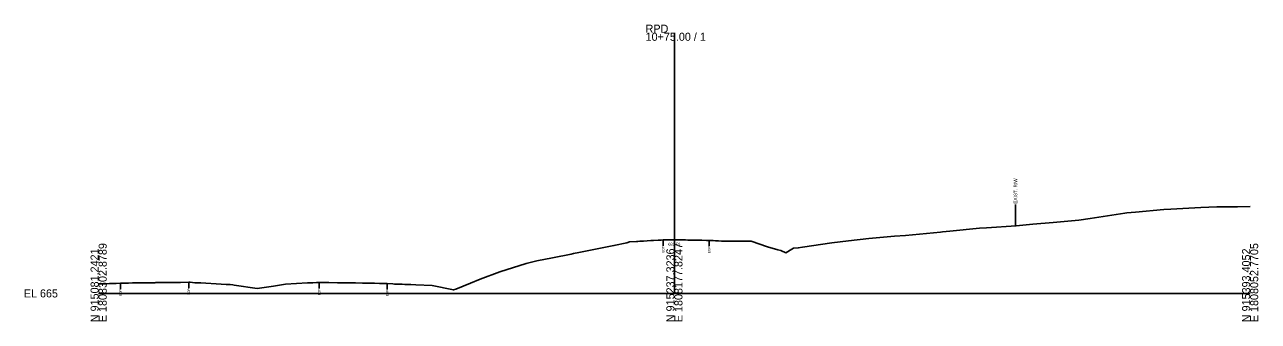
# Model space of a CAD drawing. Extents: x -26 to 403, y -10 to 8517.
# Drawn here: x -25.7 to 402.8, y 1490.3 to 1593.3 of the extents above; entities that cross this region are included whole.
import ezdxf

# ---------------------------------------------------------------- set-up
doc = ezdxf.new("R2010")
doc.units = 0
for name, color, linetype in [('Exist Cross Section Cell', 7, 'Continuous'), ('Exist XS Center Line Elevation Label', 7, 'Continuous'), ('Exist XS Ground Line', 7, 'Continuous'), ('Old_Level_10', 7, 'Continuous')]:
    doc.layers.add(name, color=color, linetype=linetype)

msp = doc.modelspace()

# ---------------------------------------------------------------- linework, layer by layer
at = {"layer": 'Exist Cross Section Cell'}
for p, q in [((200, 1500), (200, 1590.53)), ((0, 1500), (200, 1500)), ((200, 1500), (400, 1500))]:
    msp.add_line(p, q, dxfattribs=at)
at = {"layer": 'Exist XS Ground Line'}
msp.add_lwpolyline([(0, 1503.29), (0.81, 1503.31), (2.82, 1503.38), (3.79, 1503.4), (5.02, 1503.41), (6.09, 1503.46), (7.6, 1503.56), (9.3, 1503.58), (10.4, 1503.6), (11.79, 1503.62), (12.49, 1503.63), (15.66, 1503.67), (17.46, 1503.7), (18.88, 1503.73), (19.48, 1503.73), (19.82, 1503.74), (20.9, 1503.75), (22.07, 1503.77), (22.82, 1503.78), (23.76, 1503.79), (24.61, 1503.8), (25.3, 1503.81), (27.76, 1503.82), (28.47, 1503.83), (31.32, 1503.86), (31.74, 1503.85), (33.46, 1503.71), (35.11, 1503.73), (35.49, 1503.72), (42.58, 1503.25), (44.29, 1503.14), (44.97, 1503.1), (45.73, 1503.05), (46.56, 1502.99), (47.05, 1502.9), (55.02, 1501.67), (60.72, 1502.5), (64.91, 1503.2), (72.56, 1503.66), (73.06, 1503.66), (74.4, 1503.68), (75.71, 1503.74), (76.62, 1503.8), (79.99, 1503.75), (82.96, 1503.73), (83.3, 1503.73), (83.72, 1503.72), (85.06, 1503.7), (86.13, 1503.69), (86.85, 1503.68), (88, 1503.66), (88.66, 1503.65), (89.17, 1503.64), (91.69, 1503.6), (92.19, 1503.59), (92.57, 1503.58), (93.95, 1503.56), (95.82, 1503.53), (97.51, 1503.49), (98.99, 1503.46), (99.48, 1503.46), (100.27, 1503.44), (102.15, 1503.3), (102.83, 1503.25), (103.68, 1503.22), (104.64, 1503.19), (105.4, 1503.16), (106.42, 1503.12), (107.69, 1503.08), (108.44, 1503.06), (110.23, 1503), (115.82, 1502.76), (123.25, 1501.2), (124.06, 1501.51), (129.22, 1503.6), (132.55, 1504.96), (139.36, 1507.49), (148.54, 1510.35), (152.17, 1511.28), (157.67, 1512.41), (164.13, 1513.67), (164.99, 1513.81), (166.81, 1514.18), (177.8, 1516.36), (179.01, 1516.62), (183.44, 1517.62), (184.42, 1517.86), (186.82, 1518.02), (187.31, 1518.06), (188.04, 1518.1), (189.29, 1518.19), (191.84, 1518.34), (192.75, 1518.4), (194.39, 1518.46), (195.07, 1518.49), (195.45, 1518.52), (196.12, 1518.61), (196.67, 1518.6), (198.27, 1518.59), (198.89, 1518.59), (199.65, 1518.58), (200, 1518.58), (201.48, 1518.56), (203.17, 1518.56), (203.87, 1518.55), (204.68, 1518.54), (207.88, 1518.49), (209.56, 1518.46), (211.1, 1518.43), (211.52, 1518.42), (212.05, 1518.42), (213.48, 1518.33), (214.27, 1518.27), (215.36, 1518.23), (216.42, 1518.18), (217.69, 1518.18), (219.36, 1518.18), (226.72, 1518.09), (232.29, 1516.17), (235.98, 1515.15), (236.95, 1514.88), (238.66, 1514.15), (240.78, 1515.31), (241.41, 1515.68), (243.04, 1515.82), (244.5, 1516.07), (254.68, 1517.62), (260.49, 1518.25), (267.5, 1519.1), (276.49, 1519.86), (280.31, 1520.09), (292.48, 1521.26), (293.13, 1521.33), (295.73, 1521.59), (305.94, 1522.61), (308.47, 1522.81), (318.75, 1523.46), (324.47, 1524), (331.57, 1524.57), (340.46, 1525.47), (344.38, 1526.01), (356.45, 1527.88), (357.2, 1527.96), (360.19, 1528.23), (370.01, 1529.17), (372.44, 1529.3), (382.82, 1529.88), (388.44, 1530.11), (395.64, 1530.09), (400, 1530.18)], dxfattribs=at)
at = {"layer": 'Old_Level_10'}
for p, q in [((318.48, 1530.85), (318.48, 1523.44)), ((196.12, 1518.61), (196.12, 1516.56)), ((212.05, 1518.42), (212.05, 1516.37)), ((7.6, 1503.56), (7.6, 1501.51)), ((31.32, 1503.86), (31.32, 1501.81)), ((76.62, 1503.8), (76.62, 1501.75)), ((100.27, 1503.44), (100.27, 1501.39))]:
    msp.add_line(p, q, dxfattribs=at)

# ---------------------------------------------------------------- texts
at = {"layer": 'Exist Cross Section Cell'}
for s, p in [('10+75.00 / 1', (190, 1587.73)), ('RPD', (190, 1590.53)), ('EL 665', (-26, 1498.6))]:
    msp.add_text(s, height=2.8, dxfattribs=at).set_placement(p)
for s, p in [('E 1808302.8789', (2.8, 1490)), ('E 1808177.8247', (202.8, 1490)), ('E 1808052.7705', (402.8, 1490)), ('N 915081.2421', (0, 1490)), ('N 915237.3236', (200, 1490)), ('N 915393.4052', (400, 1490))]:
    msp.add_text(s, height=2.8, rotation=90, dxfattribs=at).set_placement(p)
at = {"layer": 'Exist XS Center Line Elevation Label'}
msp.add_text('683.58', height=1, dxfattribs=at).set_placement((197.86, 1516.58))
at = {"layer": 'Old_Level_10'}
for s, height, p in [('EXIST. R/W', 1.181, (319.08, 1531.15)), ('EOP', 0.787, (196.51, 1514.16)), ('EOP', 0.787, (212.45, 1513.97)), ('EOP', 0.787, (7.99, 1499.11)), ('EOP', 0.787, (31.71, 1499.42)), ('EOP', 0.787, (77.01, 1499.35)), ('EOP', 0.787, (100.66, 1498.99))]:
    msp.add_text(s, height=height, rotation=90, dxfattribs=at).set_placement(p)

doc.saveas('drawing.dxf')
